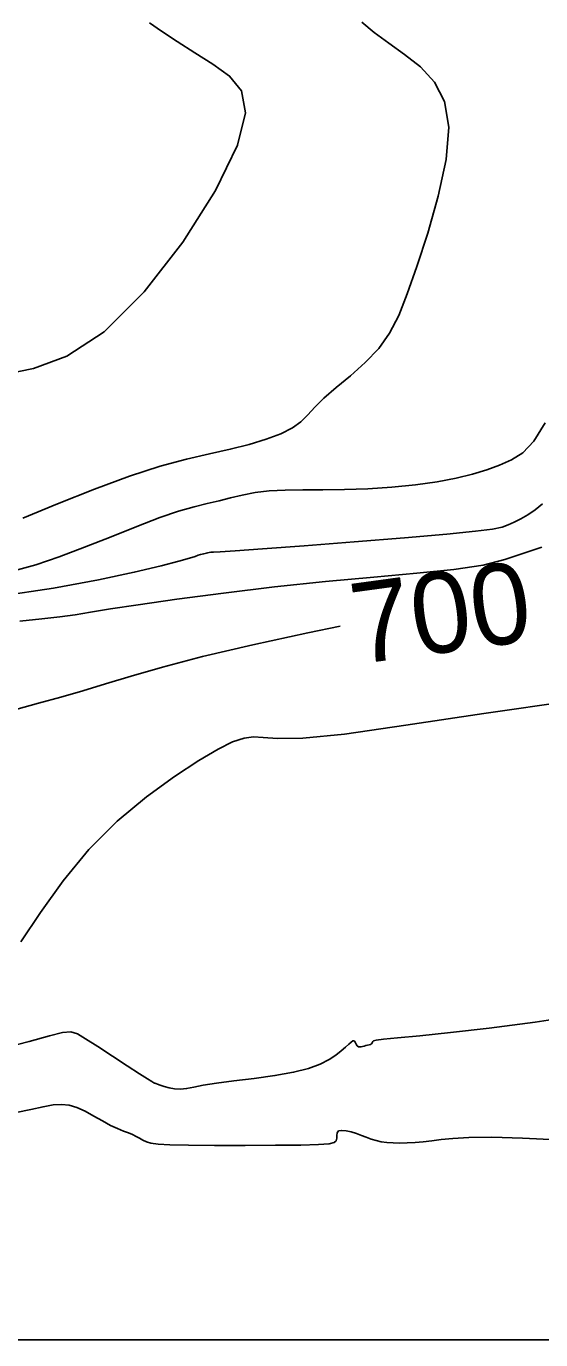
# Model space of a CAD drawing. Extents: x 2566142 to 2571431, y 418755 to 421584.
# Drawn here: x 2566746.6 to 2566874.3, y 418777.5 to 419103.3 of the extents above; entities that cross this region are included whole.
import ezdxf

# ---------------------------------------------------------------- set-up
doc = ezdxf.new("R2010")
doc.units = 0
for name, color, linetype in [('Contour_ADS_Label_Major', 7, 'Continuous'), ('Contour_ADS_Major', 7, 'Continuous'), ('Contour_ADS_Minor', 7, 'Continuous'), ('Contour_ADS_State_Plane_Border', 7, 'Continuous')]:
    doc.layers.add(name, color=color, linetype=linetype)

msp = doc.modelspace()

# ---------------------------------------------------------------- linework, layer by layer
at = {"layer": 'Contour_ADS_Major'}
for points in [[(2566741.15, 419016.93), (2566748.37, 419018.45), (2566756.7, 419021.49), (2566765.98, 419027.51), (2566775.9, 419037.43), (2566785.48, 419049.8), (2566793.57, 419062.6), (2566799.01, 419073.8), (2566801, 419081.89), (2566800.07, 419087.31), (2566797.09, 419090.99), (2566792.96, 419093.9), (2566788.46, 419096.77), (2566784.07, 419099.59), (2566780.17, 419102.14), (2566777.17, 419104.2)], [(2566790.4, 418946.95), (2566802.83, 418949.85), (2566816.52, 418952.86), (2566824.56, 418954.55)], [(2566743.98, 418933.84), (2566749.63, 418935.41), (2566755.17, 418936.92), (2566760.67, 418938.48), (2566766.29, 418940.2), (2566772.65, 418942.15), (2566780.44, 418944.38), (2566790.4, 418946.95)]]:
    msp.add_lwpolyline(points, dxfattribs=at)
at = {"layer": 'Contour_ADS_Minor'}
for points in [[(2566745.72, 418981.32), (2566754.37, 418984.83), (2566763.52, 418988.49), (2566772.27, 418991.74), (2566779.89, 418994.19), (2566786.43, 418995.95), (2566792.13, 418997.27), (2566797.25, 418998.42), (2566801.95, 418999.62), (2566806.17, 419000.89), (2566809.79, 419002.25), (2566812.68, 419003.68), (2566814.79, 419005.21), (2566816.5, 419006.9), (2566818.25, 419008.82), (2566820.5, 419011.06), (2566823.55, 419013.68), (2566827.12, 419016.64), (2566830.78, 419019.91), (2566834.12, 419023.42), (2566836.81, 419027.2), (2566839.07, 419031.59), (2566841.21, 419036.96), (2566843.56, 419043.72), (2566846.28, 419052.03), (2566848.91, 419061.2), (2566850.86, 419070.28), (2566851.51, 419078.34), (2566850.43, 419084.67), (2566847.93, 419089.49), (2566844.47, 419093.23), (2566840.55, 419096.32), (2566836.6, 419099.15), (2566832.96, 419101.8), (2566829.95, 419104.31)], [(2566743.5, 418968.27), (2566748.99, 418969.75), (2566754.76, 418971.68), (2566761.09, 418974.07), (2566767.67, 418976.7), (2566774.03, 418979.27), (2566779.73, 418981.45), (2566784.43, 418983.03), (2566788.27, 418984.12), (2566791.52, 418984.92), (2566794.46, 418985.6), (2566797.31, 418986.32), (2566800.25, 418987.03), (2566803.4, 418987.66), (2566806.9, 418988.09), (2566810.86, 418988.29), (2566815.3, 418988.33), (2566820.21, 418988.32), (2566825.6, 418988.38), (2566831.41, 418988.61), (2566837.39, 418989.01), (2566843.22, 418989.59), (2566848.61, 418990.32), (2566853.3, 418991.21), (2566857.37, 418992.21), (2566860.93, 418993.31), (2566864.13, 418994.46), (2566867.09, 418995.74), (2566869.9, 418997.55), (2566872.66, 419000.44), (2566875.47, 419004.93)], [(2566739.93, 418961.99), (2566753.33, 418963.95), (2566764.5, 418965.98), (2566773.42, 418967.88), (2566780.06, 418969.47), (2566784.48, 418970.61), (2566787.13, 418971.35), (2566788.56, 418971.81), (2566789.31, 418972.09), (2566789.85, 418972.27), (2566790.3, 418972.39), (2566790.67, 418972.49), (2566791.01, 418972.56), (2566791.34, 418972.65), (2566791.67, 418972.73), (2566792.04, 418972.8), (2566792.44, 418972.85), (2566793.06, 418972.89), (2566794.74, 418972.98), (2566798.47, 418973.22), (2566805.26, 418973.7), (2566815.61, 418974.47), (2566828.02, 418975.43), (2566840.49, 418976.43), (2566851.03, 418977.34), (2566858.15, 418978.05), (2566862.37, 418978.61), (2566864.72, 418979.11), (2566866.22, 418979.66), (2566867.73, 418980.32), (2566869.38, 418981.14), (2566871.13, 418982.15), (2566872.93, 418983.38), (2566874.78, 418984.83)], [(2566745.01, 418955.77), (2566750.45, 418956.37), (2566754.94, 418956.86), (2566758.71, 418957.36), (2566762.57, 418957.98), (2566767.48, 418958.78), (2566774.41, 418959.83), (2566783.99, 418961.19), (2566795.58, 418962.71), (2566808.22, 418964.25), (2566820.94, 418965.62), (2566832.88, 418966.71), (2566843.6, 418967.65), (2566852.78, 418968.58), (2566860.08, 418969.68), (2566865.44, 418971.04), (2566869.87, 418972.57), (2566874.65, 418974.11)], [(2566745.23, 418876.23), (2566750.16, 418883.49), (2566755.77, 418891.37), (2566762.11, 418899.12), (2566769.15, 418906.11), (2566776.43, 418912.17), (2566783.38, 418917.2), (2566789.45, 418921.15), (2566794.21, 418923.98), (2566797.84, 418925.8), (2566800.67, 418926.77), (2566803.02, 418927.06), (2566805.39, 418926.87), (2566809, 418926.62), (2566815.26, 418926.76), (2566825.58, 418927.76), (2566840.88, 418929.92), (2566860.21, 418932.84), (2566882.13, 418935.97)], [(2566832.28, 418850.93), (2566832.45, 418851.12), (2566832.57, 418851.31), (2566832.65, 418851.48), (2566832.8, 418851.63), (2566833.48, 418851.8), (2566835.28, 418852.03), (2566838.74, 418852.38), (2566844.3, 418852.92), (2566851.96, 418853.7), (2566861.57, 418854.8), (2566872.99, 418856.31), (2566885.88, 418858.24)], [(2566741.21, 418849.92), (2566747.33, 418851.51), (2566752.34, 418852.85), (2566755.6, 418853.68), (2566757.65, 418853.88), (2566759.29, 418853.4), (2566761.34, 418852.17), (2566764.38, 418850.21), (2566768.03, 418847.83), (2566771.69, 418845.45), (2566774.74, 418843.48), (2566776.73, 418842.2), (2566777.8, 418841.53), (2566778.27, 418841.26), (2566778.43, 418841.18), (2566778.56, 418841.12), (2566778.77, 418841.03), (2566779.17, 418840.88), (2566779.83, 418840.65), (2566780.81, 418840.33), (2566782.06, 418840.01), (2566783.45, 418839.75), (2566784.91, 418839.67), (2566786.4, 418839.81), (2566788.17, 418840.15), (2566790.53, 418840.61), (2566793.81, 418841.15), (2566798.18, 418841.72), (2566803.21, 418842.33), (2566808.34, 418843.03), (2566812.98, 418843.85), (2566816.71, 418844.82), (2566819.58, 418845.89), (2566821.77, 418847), (2566823.46, 418848.11), (2566824.82, 418849.14), (2566825.89, 418850.06), (2566826.71, 418850.8), (2566827.31, 418851.33), (2566827.7, 418851.61), (2566827.95, 418851.66), (2566828.12, 418851.55), (2566828.25, 418851.31), (2566828.4, 418851), (2566828.59, 418850.67), (2566828.8, 418850.38), (2566829.06, 418850.18), (2566829.36, 418850.12), (2566829.69, 418850.15), (2566830.07, 418850.25), (2566830.47, 418850.36), (2566830.9, 418850.46), (2566831.32, 418850.55), (2566831.71, 418850.65), (2566832.04, 418850.77), (2566832.28, 418850.93)], [(2566744.14, 418833.9), (2566747.73, 418834.62), (2566750.79, 418835.29), (2566753.28, 418835.74), (2566755.35, 418835.89), (2566757.23, 418835.7), (2566759.13, 418835.14), (2566761.21, 418834.19), (2566763.4, 418833), (2566765.57, 418831.77), (2566767.56, 418830.67), (2566769.28, 418829.86), (2566770.74, 418829.27), (2566771.98, 418828.82), (2566773.02, 418828.4), (2566773.91, 418827.95), (2566774.73, 418827.48), (2566775.54, 418827.02), (2566776.43, 418826.61), (2566777.55, 418826.28), (2566779.32, 418826.03), (2566782.26, 418825.85), (2566786.86, 418825.74), (2566793.36, 418825.69), (2566800.93, 418825.69), (2566808.45, 418825.73), (2566814.81, 418825.8), (2566819.18, 418825.92), (2566821.77, 418826.1), (2566823.07, 418826.4), (2566823.57, 418826.86), (2566823.71, 418827.49), (2566823.73, 418828.19), (2566823.81, 418828.83), (2566824.16, 418829.28), (2566824.92, 418829.44), (2566825.99, 418829.34), (2566827.25, 418829.06), (2566828.56, 418828.66), (2566829.82, 418828.2), (2566831.02, 418827.73), (2566832.22, 418827.28), (2566833.46, 418826.91), (2566834.76, 418826.63), (2566836.16, 418826.44), (2566837.68, 418826.34), (2566839.34, 418826.3), (2566841.16, 418826.32), (2566843.12, 418826.4), (2566845.18, 418826.56), (2566847.33, 418826.8), (2566849.62, 418827.13), (2566852.5, 418827.46), (2566856.52, 418827.69), (2566862.21, 418827.72), (2566869.82, 418827.49), (2566878.38, 418827.1)]]:
    msp.add_lwpolyline(points, dxfattribs=at)
at = {"layer": 'Contour_ADS_State_Plane_Border'}
msp.add_lwpolyline([(2566164.43, 418777.5), (2571407.81, 418777.5), (2571407.81, 421561.67), (2566164.43, 421561.67), (2566164.43, 418777.5)], close=True, dxfattribs=at)

# ---------------------------------------------------------------- texts
at = {"layer": 'Contour_ADS_Label_Major'}
msp.add_text('700', height=20, rotation=7.7725, dxfattribs=at).set_placement((2566828.71, 418945.02))

doc.saveas('drawing.dxf')
